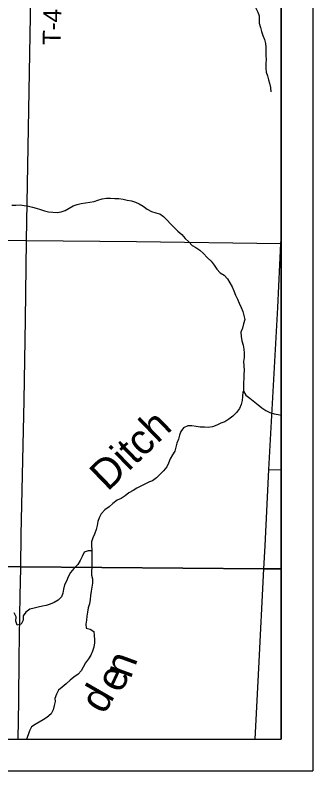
# Model space of a CAD drawing. Extents: x 0 to 34, y 0 to 22.
# Drawn here: x 8.061 to 9, y 14 to 16.386 of the extents above; entities that cross this region are included whole.
import ezdxf

# ---------------------------------------------------------------- set-up
doc = ezdxf.new("R2010")
doc.units = 0
for name, color, linetype in [('GM_X_Corporation', 7, 'Continuous'), ('GM_X_County_Road', 7, 'Continuous'), ('GM_X_Minor_River', 7, 'Continuous'), ('GM_X_Minor_River_Text', 7, 'Continuous'), ('GM_X_State_Route', 7, 'Continuous'), ('GM_X_Township_Road', 7, 'Continuous'), ('GM_X_Township_Road_Text', 7, 'Continuous'), ('SH_Data', 7, 'Continuous')]:
    doc.layers.add(name, color=color, linetype=linetype)

msp = doc.modelspace()

# ---------------------------------------------------------------- linework, layer by layer
at = {"layer": 'GM_X_Corporation'}
msp.add_lwpolyline([(7.0838, 16.6084), (7.1072, 15.3824), (7.118, 14.8105), (7.1215, 14.6514), (7.1267, 14.4123), (7.1269, 14.4049), (7.1335, 14.1), (8.9, 14.1), (8.9, 20.9)], dxfattribs=at)
for points in [[(8.9, 14.638), (8.9, 19.8484), (8.3424, 19.8533), (7.6795, 19.8561), (7.3272, 19.8568), (7.1717, 19.8568), (7.0046, 19.8599), (7.0077, 19.6756), (7.0107, 19.4664), (7.0305, 18.5559), (7.0429, 18.0629), (7.0494, 17.8247), (7.0577, 17.449), (7.0649, 17.2134), (7.0651, 17.204), (7.0717, 16.9849), (7.0838, 16.6084), (7.1072, 15.3824), (7.118, 14.8105), (7.1215, 14.6514), (7.384, 14.6494), (8.0793, 14.6442), (8.8452, 14.6384)], [(7.1335, 14.1), (8.9, 14.1), (8.9, 14.638), (8.8452, 14.6384), (8.0793, 14.6442), (7.384, 14.6494), (7.1215, 14.6514), (7.1267, 14.4123), (7.1269, 14.4049)]]:
    msp.add_lwpolyline(points, close=True, dxfattribs=at)
at = {"layer": 'GM_X_County_Road'}
msp.add_line((8.8609, 14.9515), (8.9, 14.9509), dxfattribs=at)
at = {"layer": 'GM_X_Minor_River'}
for points in [[(8.8181, 16.4208), (8.8203, 16.4082), (8.8265, 16.3952), (8.8306, 16.3833), (8.8304, 16.3738), (8.831, 16.3601), (8.8346, 16.3471), (8.8383, 16.3338), (8.8427, 16.3215), (8.847, 16.3089), (8.8503, 16.2967), (8.8517, 16.2849), (8.8519, 16.272), (8.8513, 16.2587), (8.853, 16.2457), (8.8517, 16.2328), (8.8515, 16.2187), (8.8529, 16.2062), (8.8565, 16.1943), (8.8605, 16.1813), (8.8634, 16.1714), (8.8666, 16.1577), (8.868, 16.1443)], [(8.0505, 15.7856), (8.0635, 15.7862), (8.0772, 15.7867), (8.0897, 15.785), (8.103, 15.7829), (8.1156, 15.7801), (8.1281, 15.7761), (8.141, 15.7724), (8.1535, 15.7685), (8.166, 15.7648), (8.1797, 15.7635), (8.1934, 15.7629), (8.2063, 15.7654), (8.219, 15.769), (8.232, 15.776), (8.2447, 15.7838), (8.2569, 15.7882), (8.2695, 15.791), (8.297, 15.7952), (8.31, 15.798), (8.3222, 15.8016), (8.3352, 15.8056), (8.349, 15.8085), (8.3619, 15.8083), (8.3756, 15.8073), (8.3885, 15.8067), (8.4018, 15.8046), (8.4147, 15.8021), (8.428, 15.7997), (8.4409, 15.7953), (8.4526, 15.7902), (8.4647, 15.7827), (8.4779, 15.7738), (8.4915, 15.7664), (8.5044, 15.762), (8.5173, 15.7591), (8.5294, 15.7506), (8.5406, 15.739), (8.5508, 15.7274), (8.5631, 15.7151), (8.5744, 15.7039), (8.5872, 15.6934), (8.5973, 15.6811), (8.6086, 15.6707), (8.6195, 15.6587), (8.6308, 15.6525), (8.6436, 15.6443), (8.6553, 15.6338), (8.6669, 15.6211), (8.6793, 15.6091), (8.689, 15.5968), (8.6969, 15.5842), (8.7081, 15.5726), (8.7206, 15.5655), (8.7311, 15.5532), (8.7381, 15.5406), (8.746, 15.5283), (8.7507, 15.5153), (8.7563, 15.5023), (8.7622, 15.4892), (8.7677, 15.4762), (8.774, 15.4632), (8.7791, 15.4502), (8.7828, 15.438), (8.7853, 15.425), (8.7813, 15.411), (8.778, 15.3977), (8.7733, 15.3849)], [(8.7733, 15.3849), (8.7735, 15.3712), (8.776, 15.3575), (8.78, 15.3445), (8.7821, 15.3315), (8.783, 15.3186), (8.7836, 15.3049), (8.7811, 15.292), (8.7828, 15.2783), (8.7834, 15.2646), (8.7825, 15.2517), (8.7819, 15.2387), (8.781, 15.2262), (8.7816, 15.2129), (8.781, 15.1992), (8.7888, 15.1865), (8.8012, 15.1765), (8.8276, 15.1555), (8.8389, 15.1466), (8.8513, 15.1381), (8.8642, 15.1318), (8.8775, 15.1274), (8.8907, 15.1249), (8.9, 15.1229)], [(8.781, 15.1992), (8.7797, 15.1957), (8.7785, 15.1821), (8.7771, 15.1696), (8.7739, 15.1571), (8.7684, 15.1443), (8.7591, 15.1315), (8.7475, 15.1203), (8.7348, 15.1106), (8.7225, 15.1024), (8.7095, 15.0973), (8.6969, 15.0914), (8.6831, 15.0866), (8.6701, 15.0845), (8.658, 15.0851), (8.6442, 15.0853), (8.6317, 15.0874), (8.6188, 15.0895), (8.6055, 15.089), (8.5921, 15.0827), (8.5839, 15.0714), (8.5799, 15.0597), (8.576, 15.0476), (8.5716, 15.0347), (8.5676, 15.0218), (8.5644, 15.0097), (8.5577, 14.9973), (8.5503, 14.9848), (8.5452, 14.9716), (8.5397, 14.9595), (8.5289, 14.9472), (8.5181, 14.9363), (8.5069, 14.9247), (8.4942, 14.9157), (8.4846, 14.9121), (8.4723, 14.9058), (8.4581, 14.8992), (8.4455, 14.8925), (8.4332, 14.8855), (8.4202, 14.8781), (8.4082, 14.8684), (8.3952, 14.8598), (8.3825, 14.8543), (8.3698, 14.8446), (8.3575, 14.8338), (8.3437, 14.8241), (8.3321, 14.8117), (8.3258, 14.7993), (8.3218, 14.7872), (8.3197, 14.7747), (8.3165, 14.7618), (8.311, 14.7478), (8.3062, 14.7353), (8.3019, 14.7229), (8.3017, 14.7092), (8.3027, 14.6996), (8.3033, 14.6901), (8.3035, 14.6764), (8.3032, 14.6536), (8.3027, 14.6415), (8.3018, 14.632), (8.3023, 14.6183), (8.3048, 14.6061), (8.305, 14.5928), (8.3033, 14.5799), (8.3012, 14.567), (8.2988, 14.5533), (8.2975, 14.5412), (8.2961, 14.5279), (8.2914, 14.5147), (8.2893, 14.5014), (8.2876, 14.4881), (8.2863, 14.476), (8.2842, 14.4631), (8.2852, 14.4501), (8.2977, 14.4469), (8.309, 14.4399), (8.3103, 14.4277), (8.3117, 14.414), (8.3115, 14.4045), (8.3091, 14.3908), (8.3051, 14.378), (8.3, 14.3655), (8.2926, 14.3538), (8.2829, 14.3407), (8.2758, 14.3275), (8.2692, 14.3154), (8.2595, 14.3049), (8.2468, 14.2956), (8.2349, 14.2863), (8.2218, 14.2747), (8.2095, 14.2638), (8.1979, 14.2549), (8.192, 14.2421), (8.1869, 14.2288), (8.1871, 14.2193), (8.1839, 14.2064), (8.1807, 14.1932), (8.1744, 14.1804), (8.1613, 14.1688), (8.1498, 14.161)], [(8.303, 14.6951), (8.2912, 14.6945), (8.279, 14.6901), (8.2723, 14.6765), (8.266, 14.6645), (8.2586, 14.6516), (8.2467, 14.6389), (8.2358, 14.6261), (8.2284, 14.6129), (8.2233, 14.5993), (8.217, 14.5869), (8.2142, 14.574), (8.2113, 14.5615), (8.2077, 14.549), (8.1969, 14.5389), (8.1843, 14.5319), (8.1716, 14.5267), (8.159, 14.5224), (8.1472, 14.5195), (8.1342, 14.517), (8.1212, 14.5142), (8.1074, 14.511), (8.0955, 14.5009), (8.087, 14.4896), (8.0864, 14.4759), (8.0805, 14.4635), (8.0675, 14.4603), (8.0635, 14.4729), (8.0645, 14.4865), (8.0578, 14.4988)], [(8.1498, 14.161), (8.1367, 14.1539), (8.1245, 14.1469), (8.1125, 14.1391), (8.1063, 14.1266), (8.1019, 14.1142), (8.0975, 14.1005), (8.0975, 14.1)]]:
    msp.add_lwpolyline(points, dxfattribs=at)
at = {"layer": 'GM_X_State_Route'}
for points in [[(8.8609, 14.9515), (8.8894, 15.4631), (8.8994, 15.6654), (8.9, 15.6769)], [(8.8186, 14.1), (8.8299, 14.3245), (8.8454, 14.6379), (8.8491, 14.7108), (8.8609, 14.9515)]]:
    msp.add_lwpolyline(points, dxfattribs=at)
at = {"layer": 'GM_X_Township_Road'}
for points in [[(8.097, 15.6749), (8.1117, 16.5015), (8.1119, 16.5123)], [(7.3381, 15.6814), (7.5702, 15.6792), (7.9034, 15.6768), (8.097, 15.6749)], [(8.0794, 14.6397), (8.0795, 14.6436), (8.0805, 14.7455), (8.0893, 15.1691), (8.0936, 15.4255), (8.097, 15.6749)], [(8.097, 15.6749), (8.4437, 15.6718), (8.8994, 15.6654)], [(8.0707, 14.1), (8.0726, 14.2199), (8.0738, 14.3576), (8.0774, 14.5536), (8.0794, 14.6397)]]:
    msp.add_lwpolyline(points, dxfattribs=at)
at = {"layer": 'SH_Data'}
for p, q in [((9, 21), (9, 14)), ((8.9, 20.9), (8.9, 14.1)), ((2.1, 14.1), (8.9, 14.1)), ((2, 14), (9, 14))]:
    msp.add_line(p, q, dxfattribs=at)

# ---------------------------------------------------------------- texts
at = {"layer": 'GM_X_Minor_River_Text'}
for s, height, rotation, p in [('Ditch', 0.09474, 43.9946, (8.353, 14.8801)), ('n', 0.0947, 69.9928, (8.4252, 14.2879)), ('e', 0.0947, 64.9923, (8.3955, 14.2424)), ('d', 0.0947, 59.992, (8.3421, 14.1757))]:
    msp.add_text(s, height=height, rotation=rotation, dxfattribs=at).set_placement(p)
at = {"layer": 'GM_X_Township_Road_Text'}
msp.add_text('T-47', height=0.05682, rotation=88.9383, dxfattribs=at).set_placement((8.2047, 16.2908))

doc.saveas('drawing.dxf')
